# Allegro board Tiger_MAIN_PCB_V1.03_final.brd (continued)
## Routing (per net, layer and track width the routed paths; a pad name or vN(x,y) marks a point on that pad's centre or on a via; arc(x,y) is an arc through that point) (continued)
WIFI_PCIE_CLK_DP: length 146.9
  TOP w0.076: U1.C41 210.39,76.48 210.31,76.55 210.31,76.74 210.53,76.96 210.53,77.5 210.98,77.94 210.98,78.79 210.77,78.99 210.65,78.99 210.35,79.28 v2(210.35,79.37)
  TOP w0.109: v2(127.92,49.22) 127.73,49.03 127.73,36.09 127.07,35.43 127.07,30.21 127.43,29.86 127.43,26.24 126.18,25 125.29,25 125.15,24.86 CN26.47
  LAY6 w0.076: 189.88,79.4 195.09,79.4 195.83,80.15 201.63,80.15 202.57,81.09 202.57,81.37 202.84,81.64 204.11,81.64 206.24,79.51 207.45,79.51 207.98,78.98 209.96,78.98 v2(210.35,79.37)
  LAY6 w0.087: 189.88,79.4 181.76,79.4 180.68,80.48 176.34,80.48 174.97,79.11 172.69,79.11 171.94,79.87 168.04,79.87 167.59,80.32 164.72,80.32 164.05,79.64 160.51,79.64 158.5,77.64 150.89,77.64 149.24,75.99 144.86,75.99 144.08,75.21 134.96,75.21 134.65,75.52 129.16,75.52 128.96,75.72 128.96,76.09 v2(129.19,76.32)
  BOTTOM w0.109: v2(129.19,76.32) 128.96,76.1 128.96,75.44 127.73,74.2 127.73,49.41 v2(127.92,49.22)
WIFI_POWERON: length 113.7
  LAY3 w0.102: v2(63.45,63.17) 64.66,61.96 64.66,58.68 63.91,57.93 v2(63.91,35.78)
  LAY6 w0.102: v2(63.91,35.78) 64.31,36.18 78.61,36.18 79.01,35.77 80.7,35.77 81.73,36.8 84.4,36.8 91.01,43.42 93.67,43.42 97.68,47.43 107.03,47.43 109.12,45.33 112.37,45.33 114.69,43.02 118.26,43.02 118.88,42.4 127.4,42.4 134.85,34.95 v2(134.85,34.19)
  BOTTOM w0.102: v2(63.45,63.17) 63.16,63.46 U22.18 ; U19.3 135.39,34.19 R378.1 v2(134.85,34.19)
WIFI_RF_KILL_R*: length 3
  TOP w0.102: CN26.56 133.12,27.11 v2(133.3,26.92)
  BOTTOM w0.102: R3005.1 133.68,27.3 v2(133.3,26.92)
WIRELESS_ON: length 99.3
  LAY6 w0.102: v2(136.14,27.3) 136.14,27.31 136.62,27.8 136.62,33.89 127.39,43.12 119.44,43.12 119,43.56 115.02,43.56 112.67,45.91 109.95,45.91 107.82,48.04 97.06,48.04 93.71,44.69 86.96,44.69 86.05,45.6 66.63,45.6 61.63,50.61 v2(60.3,50.61)
  BOTTOM w0.102: U22.33 60.32,50.62 v2(60.3,50.61) ; R3005.2 v2(136.14,27.3)
WLAN_PCIE_WAKE*: length 104.5
  TOP w0.102: v2(190.56,59.53) 190.2,59.89 U1.AP7
  TOP w0.109: R95.2 172.96,59.18 v2(172.99,59.15) ; v2(120.8,55.47) 120.8,50.53 118.22,47.95 118.22,30.39 120.72,27.88 R3127.1
  LAY3 w0.076: 176.13,60.06 176.44,60.37 184.95,60.37 185.79,59.53 v2(190.56,59.53)
  LAY3 w0.087: 176.13,60.06 175.23,59.15 v2(172.99,59.15)
  LAY6 w0.087: v2(172.99,59.15) 172.24,58.4 166.72,58.4 165.91,57.59 164.71,57.59 163.9,58.4 160.01,58.4 159.28,57.67 ; 154.89,55.74 154.31,55.15 147.77,55.15 147.06,55.86 121.19,55.86 v2(120.8,55.47)
  LAY6 w0.102: 159.28,57.67 156.82,57.67 154.89,55.74
WLAN_PLT_RST: length 5.6
  TOP w0.102: v2(133.16,26.11) 133.11,26.11 133.11,26.11 CN26.52
  BOTTOM w0.102: U18.4 136.76,26.96 136.18,26.38 R155.1 133.44,26.38 v2(133.16,26.11)
WRST#: length 2.9
  TOP w0.102: v2(60.76,65.01) 60.76,64.69 61.04,64.41 R408.1 C481.2
  BOTTOM w0.102: U22.14 60.81,65.06 v2(60.76,65.01)
XCLK_BIASREF: length 9.4
  TOP w0.076: U1.E42 v2(210.68,74.32)
  TOP w0.102: v2(209.2,81.9) 209.82,81.9 R4.2
  LAY3 w0.102: v2(209.2,81.9) 209.85,81.25 209.85,75.15 v2(210.68,74.32)
XDP_BPM<2>: length 10.1
  TOP w0.076: TP22.1 218.61,83.82 218.61,79.65 217.71,78.75 217.71,77.2 U1.B54
XDP_BPM<3>: length 9.5
  TOP w0.076: TP23.1 219.22,83.43 219.22,79.54 218.17,78.49 218.17,76.42 U1.C56
XTAL1: length 9.2
  BOTTOM w0.102: U9.43 125.6,37.15 124.01,35.56 124.01,35.42 C372.1 124.28,35.08 123.86,34.65 123.86,30.89 X3.1
XTAL2: length 7.4
  BOTTOM w0.102: X3.3 123.61,32.52 123.61,34.62 C371.1 125.2,37.12 U9.44
XTAL24_IN: length 12.6
  TOP w0.102: U1.E37 208.23,75.49 208.23,75.62 208.25,75.64 208.25,76.01 208.23,76.03 208.23,76.27 208.25,76.29 208.25,76.6 207.92,76.93 207.92,77.88 207.6,78.19 207.6,78.45 207.38,78.67 207.38,81.77 R3.1 207.52,82.12 C1.1 207.52,83.2 207.1,83.61 207.1,84.75 X1.3
XTAL24_OUT: length 10.9
  TOP w0.102: X1.1 206.69,83.41 C2.1 206.69,82.03 R3.2 207.1,81.59 207.1,78.56 207.31,78.35 207.31,78.04 207.67,77.68 207.67,76.29 207.69,76.27 207.69,76.03 207.67,76.01 207.67,75.71 207.69,75.68 207.69,75.38 207.38,75.07 206.9,75.07 U1.E35
N26714753: length 9.3
  TOP w0.076: U1.BA15 195.07,55.33 195.33,55.08 195.33,53.98 191.37,50.02 191.37,49.35 190.95,48.93 R24.1 R9.2
N26714785: length 19.5
  TOP w0.076: U1.AN15 194.74,60.54 v2(195.13,60.15)
  TOP w0.102: R616.1 v2(181.33,52.26)
  LAY6 w0.076: v2(195.13,60.15) 194.63,59.65 193.97,59.65 193.66,59.34 193.66,57.54 191.15,55.02 185.79,55.02 185.26,54.49 184.51,54.49 182.22,52.2 181.7,52.2
  LAY6 w0.102: v2(181.33,52.26) 181.39,52.2 181.7,52.2
N26722992: length 14.5
  TOP w0.076: v2(177.24,70.03) 176.86,70.41 R56.1 ; v2(189.63,70.08) U1.N7
  LAY6 w0.076: v2(189.63,70.08) 189.18,70.54 188.09,70.54
  LAY6 w0.102: 188.09,70.54 184.32,70.54 183.86,71 178.21,71 v2(177.24,70.03)
N26723031: length 14.6
  TOP w0.076: R55.1 177.66,70.17 v2(177.8,70.03) ; U1.N8 v2(190.27,70.08)
  LAY6 w0.076: v2(190.27,70.08) 189.9,69.72 188.68,69.72 188.13,70.26
  LAY6 w0.102: 188.13,70.26 184.07,70.26 183.58,70.76 178.53,70.76 v2(177.8,70.03)
N26739346: length 12.2
  TOP w0.254: U1.G20 197.34,73.43 v2(196.96,73.05)
  LAY6 w0.254: v2(199.17,78.71) 198.75,78.29 198.75,75.75 199.26,75.24 199.26,74.43 198.01,73.19 197.1,73.19 v2(196.96,73.05)
  BOTTOM w0.305: v2(199.17,78.71) 199.19,78.74 199.19,80.42 198.66,80.96 R123.1
N26757648: length 3.8
  TOP w0.102: R711.2 176.21,51.1 R707.2 176.53,50.77 U42.7
N26757763: length 4.1
  TOP w0.102: U42.3 177.8,40.05 177.29,39.54 177.29,38.49 R709.2 R136.2
N26757791: length 3.2
  TOP w0.102: U42.2 176.53,38.96
  TOP w0.109: 176.53,38.96 R138.2
N26757807: length 2.9
  TOP w0.102: R139.2 179.06,48.25 U42.5
N26757835: length 7
  TOP w0.102: U42.6 177.8,46.75 177.98,46.57 178.3,46.57 178.47,46.73 178.47,50.48 R137.2
N29995527: length 9.8
  TOP w0.076: R75.2 182.9,52.44 184.43,53.97 186.78,53.97 187.33,54.52 187.33,55.05 187.5,55.22 187.5,55.56 187.7,55.76 187.97,55.76 188.11,55.9 188.11,56.46 188.87,57.23 U1.AW5
N30351746: length 7.6
  TOP w0.076: v2(220.42,82.71) 219.62,81.91 219.62,79.46 218.66,78.49 218.65,78.49 218.55,78.4 218.55,78.39 218.52,78.35 218.52,77.79 218.7,77.61 218.7,77.34 218.64,77.23 218.64,77.01 U1.B56
  BOTTOM w0.102: R39.2 220,82.71 v2(220.42,82.71)
N30351752: length 7.3
  TOP w0.076: v2(220.42,80.76) 220.03,80.36 220.03,79.36 219.51,78.85 219.51,77.83 219.36,77.68 219.36,77.32 219.39,77.22 219.39,77.03 219.36,76.94 219.36,76.69 219.37,76.64 219.41,76.49 219.49,76.21 219.49,76.09 219.57,75.83 U1.D59
  BOTTOM w0.102: R35.1 220.84,81.49 220.84,81.18 v2(220.42,80.76)
N30351756: length 8.5
  TOP w0.076: U1.A56 218.34,77.55 218.34,78.42 219.42,79.51 219.42,82.35 v2(220.42,83.36)
  BOTTOM w0.076: v2(220.42,83.36) 221.49,84.42 R31.1
N30351760: length 6.7
  TOP w0.076: U1.C59 219.6,76.46 219.52,76.71 219.52,76.89 219.58,77.08 219.58,77.23 219.52,77.34 219.52,77.61 219.69,77.78 219.69,78.73 220.41,79.45 220.41,80.09 v2(220.42,80.11)
  BOTTOM w0.102: R30.1 220.04,81.65 220.04,80.49 v2(220.42,80.11)
N30351779: length 6.4
  TOP w0.076: v2(222.23,80.76) 221.79,80.32 221.79,79.16 221.01,78.37 221.01,77.78 221.18,77.61 221.18,77.34 221.12,77.23 221.12,77.01 U1.B61
  BOTTOM w0.102: R40.2 222.7,81.58 222.7,81.23 v2(222.23,80.76)
N30351789: length 10.4
  TOP w0.076: R32.1 222.02,84.45 221.63,84.06 221.63,82.46 221.22,82.05 221.22,79.56 220.28,78.62 220.28,76.82 220.06,76.6 220.06,76.36 U1.D60
N30351793: length 6.5
  TOP w0.076: U1.A61 220.83,77.54 220.83,78.42 221.63,79.22 221.63,80.8 v2(222.23,81.41)
  BOTTOM w0.102: R33.1 222.6,82.34 222.6,81.77 v2(222.23,81.41)
N30351797: length 9
  TOP w0.076: R34.1 222.57,83.68 222.4,83.86 222.08,83.86 221.8,83.57 221.8,82.39 221.43,82.02 221.43,79.49 220.44,78.51 220.44,76.57 U1.C60
N30351801: length 20
  TOP w0.076: v2(222.23,82.06) 222.63,81.66 222.63,79.75 221.74,78.87 221.17,78.3 221.17,77.85 221.35,77.68 221.35,77.31 221.33,77.28 221.31,77.22 221.31,76.61 221.3,76.6 221.3,76.54 U1.C61 ; U1.B59 220.11,77.13 220.11,78.7 221.02,79.61 221.02,82.14 221.47,82.59 221.47,84.55 v2(222.23,85.31)
  LAY3 w0.102: v2(222.23,85.31) 221.86,84.93 221.86,82.43 v2(222.23,82.06)
N30362590: length 20.7
  TOP w0.102: v2(190.56,58.88) 190.2,59.24 U1.AR7
  TOP w0.109: v2(172.9,57.89) 172.97,57.96 R97.1
  LAY6 w0.076: 176.13,59.33 181.15,59.33 182.09,58.39 186.31,58.39 187.52,59.59 189.85,59.59 v2(190.56,58.88)
  LAY6 w0.087: v2(172.9,57.89) 174.3,57.89 175.74,59.33 176.13,59.33
N30362783: length 12.5
  TOP w0.076: U1.AD11 192.51,65.05 v2(192.81,64.75)
  BOTTOM w0.102: v2(192.81,64.75) 192.43,64.37 188.67,64.37 188.35,64.68 187.27,64.68 185.93,63.34 R98.2
N30362785: length 16.2
  TOP w0.076: U1.AD12 193.16,65.03 v2(193.44,64.75)
  BOTTOM w0.102: v2(193.44,64.75) 192.88,64.18 188.58,64.18 188.29,64.47 187.35,64.47 185.97,63.09 182.56,63.09 182.37,62.91 179.41,62.91 R99.2
N30362889: length 5
  TOP w0.076: U1.AN5 188.75,60.98 184.87,60.98 R101.1
N30418600: length 1.9
  TOP w0.076: U1.AK62 221.3,62.25 v2(220.16,63.38)
N30418602: length 1.2
  TOP w0.076: U1.AL61 220.73,62.12 220.21,62.64 v2(220.16,62.64)
N30475256: length 0.6
  TOP w0.076: U1.AM23 v2(200.62,60.8)
N30475258: length 1.8
  TOP w0.076: v2(199.7,60.8) U1.AM22
  BOTTOM w0.102: v2(199.7,60.8) 200.15,61.25 TP40.1
N30589381: length 2
  TOP w0.102: U6.1 169.42,54.3 R662.2 R663.1
N30589405: length 1.6
  TOP w0.203: C688.2 168.21,58.96 168.69,58.96 168.91,59.19 U67.6
N31076332: length 8.9
  TOP w0.076: U1.AW22 198.69,56.68 198.86,56.5 198.86,56.5 199.08,55.8 199.08,55.72 199.14,55.56 199.14,55.41 199.07,55.2 199.07,55.08 199.11,55 199.12,54.97 199.12,54.52 198.77,54.17 198.77,53.98 198.32,53.53 198.32,51.32 197.83,50.83 R623.2 R69.2
N31079742: length 4.7
  TOP w0.076: U1.BB5 188.93,54.7 188.61,54.7 188.06,54.16 187.58,54.16 186.67,53.25 TP43.1
N32032184: length 17.5
  TOP w0.076: U1.U6 v2(188.98,67.95)
  TOP w0.109: R111.2 174.2,67.79 v2(173.64,67.79)
  LAY3 w0.076: v2(188.98,67.95) 189.06,67.87 189.06,67.63 188.92,67.49 184.46,67.49 184.32,67.36 176.22,67.36
  LAY3 w0.102: v2(173.64,67.79) 174.07,67.36 176.22,67.36
N32032194: length 19.6
  TOP w0.076: U1.U7 v2(189.63,67.95)
  TOP w0.109: R110.2 174.01,66.79 v2(173.03,67.77)
  LAY3 w0.076: 176.13,67.07 184.27,67.07 184.51,67.31 189,67.31 v2(189.63,67.95)
  LAY3 w0.102: 176.13,67.07 173.72,67.07 v2(173.03,67.77)
N32032416: length 24
  TOP w0.076: v2(193.44,63.68) 193.16,63.97 U1.AF12
  TOP w0.109: v2(173.61,60.02) 173.07,60.56 R107.2
  LAY6 w0.076: 176.13,59.66 181.4,59.66 182.38,58.68 185.72,58.68 187.1,60.07 189.35,60.07 190.23,60.94 190.87,60.94 193.44,63.51 v2(193.44,63.68)
  LAY6 w0.102: 176.13,59.66 173.97,59.66 v2(173.61,60.02)
N32032433: length 23.2
  TOP w0.076: U1.AF11 192.51,63.98 v2(192.81,63.68)
  TOP w0.109: R106.2 173.63,60.74 v2(173.63,60.61)
  LAY6 w0.076: v2(192.81,63.68) 192.81,63.15 190.8,61.13 190.18,61.13 189.79,60.74 186.96,60.74 185.83,59.61 182.19,59.61 181.81,59.99 176.13,59.99
  LAY6 w0.102: v2(173.63,60.61) 174.25,59.99 176.13,59.99
N32034483: length 14.8
  TOP w0.076: U1.U8 v2(190.24,67.95)
  TOP w0.102: v2(178.44,68.33) 178.44,68.16 R108.2
  LAY6 w0.076: v2(178.44,68.33) 178.27,68.33 178.11,68.18 178.11,67.98 178.45,67.64 188.62,67.64 188.74,67.53 190.23,67.53 190.39,67.68 190.39,67.8 v2(190.24,67.95)
N32034499: length 15.3
  TOP w0.076: U1.U9 v2(190.89,67.95)
  TOP w0.102: v2(177.79,68.33) 177.59,68.53 177.59,68.63 R109.2
  LAY6 w0.076: v2(177.79,68.33) 177.79,68.04 178.37,67.46 188.57,67.46 188.68,67.35 190.29,67.35 v2(190.89,67.95)
N32256786: length 7.2
  TOP w0.102: U1.AW50 215.05,56.55 215.05,53.97 216.21,52.81 R3124.1
N32703185: length 10.8
  TOP w0.076: U1.B63 222.59,77.13 222.59,78.72 223.36,79.49 223.36,80.56 224.53,81.72 226.28,81.72 226.84,81.16 228.18,81.16 228.43,81.4 228.43,82.15 R122.2
N32759666: length 7.4
  TOP w0.076: v2(227.18,79.92) 226.7,79.92 226.32,80.31 224.55,80.31 224.08,79.84 224.08,79.2 223.3,78.41 223.3,77.8 223.28,77.79 223.28,77.68 223.39,77.57 U1.A65
  BOTTOM w0.102: TP21.1 227.23,79.97 v2(227.18,79.92)
N32938866: length 0.7
  TOP w0.102: U1.K32 v2(204.73,71.76)
N32938875: length 0.7
  TOP w0.102: U1.AK32 v2(204.73,62.87)
N32946040: length 6.2
  TOP w0.076: U1.BA5 189.13,55.3 189.32,55.1 189.32,54.67 189.17,54.51 188.69,54.51 188.14,53.97 187.67,53.97 185.81,52.11 185.81,51.9 R37.2
N33185602: length 1.8
  TOP w0.102: R827.2 171.01,80.62 R828.2 171.26,81.4 171.46,81.2 U56.3
N33386131: length 7
  TOP w0.076: TP45.1 181.96,70.36 181.96,69.85 182.3,69.5 185.14,69.5 185.69,68.95 186.86,68.95 U1.U2
N33386639: length 5.9
  TOP w0.076: TP44.1 181.98,69.34 183.93,69.34 184.49,68.78 R118.1
  TOP w0.102: R118.1 185.55,68.45 185.74,68.64 U1.U1
N33387416: length 4
  TOP w0.076: U1.N3 187.94,70.63 187.7,70.86 187.58,70.9 187.45,70.9 187.44,70.9 187.22,70.84 187.09,70.84 186.96,70.89 186.95,70.9 186.75,70.9 186.63,70.84 184.98,70.84 R117.1
N33387421: length 4.2
  TOP w0.076: U1.M4 188.21,71.02 187.74,71.02 187.59,71.08 187.44,71.08 187.22,71.01 187.11,71.01 186.99,71.06 186.97,71.08 186.76,71.08 186.57,71 184.67,71 R116.1
N34176799: length 11
  TOP w0.076: U1.C65 223.74,76.5 223.74,76.5 arc(223.81,76.58) 223.83,76.69 223.83,76.95 223.78,77.07 223.78,77.18 223.78,77.19 223.82,77.23 223.82,77.68 223.69,77.8 223.69,78.27 224.74,79.33 230.77,79.33 231.12,79.68 R36.2
N34374288: length 0.8
  BOTTOM w0.203: C7.1 R48.2
N34404832: length 0.8
  BOTTOM w0.203: C8.1 R49.2
N34544097: length 0.9
  TOP w0.109: C412.1 18.53,92.04 FIL7.1
N34544176: length 4.1
  TOP w0.109: D8.N 8.53,90.56 FIL5.3
  TOP w0.124: CN36.3 7.95,92.97 8.85,92.07 8.85,91.84 D8.N
N34544206: length 7.3
  TOP w0.109: FIL7.2 15.5,91.68 15.11,91.68 U14.2 14.72,92.07 13.94,92.07 13.31,91.44 12.28,91.44 12.04,91.69 12.04,91.99 12.95,92.91 CN36.9
N34544208: length 7.3
  TOP w0.109: CN36.8 10.95,92.92 11.82,92.06 11.82,91.6 12.19,91.22 13.52,91.22 13.84,90.9 14.69,90.9 U14.1 15.76,91.15 FIL7.3
N34544223: length 4.1
  TOP w0.109: D7.N 9.43,90.55 FIL5.2
  TOP w0.124: D7.N 9.11,91.84 9.11,92.11 9.95,92.96 CN36.2
N34544234: length 3.6
  TOP w0.109: U13.1 5.55,90.97 FIL6.3
  TOP w0.124: U13.1 4.95,92.14 CN36.5
N34544244: length 0.9
  TOP w0.109: C411.1 18.53,91.04 FIL7.4
N34544271: length 3.7
  TOP w0.109: FIL6.2 6.25,90.9 U13.2
  TOP w0.124: U13.2 6.95,92.25 CN36.6
N34559149: length 0.5
  BOTTOM w0.203: R429.2 127.82,82.38
N34559202: length 2.1
  BOTTOM w0.102: C490.2 129.23,81.57 R429.1 129.23,82.38 U25.4
N34566306: length 7.8
  BOTTOM w0.152: U22.2 60.93,69.86 60.75,70.03 60.75,70.56 61.8,71.61 61.8,72.56 R425.1 62.95,73.05 C484.1 63.5,73.18 63.73,72.95 X5.2
N34566379: length 8.3
  BOTTOM w0.152: X5.1 65.01,74 63.12,74 C482.1 63.02,74 R425.2 R424.2 61.5,73.99 61.5,71.69 60.68,70.87 60.45,70.87 60.32,71 U22.128
N34566418: length 3.4
  BOTTOM w0.102: U22.21 62.54,62.26 62.73,62.45 64.79,62.45 R416.1
N34566506: length 2
  BOTTOM w0.102: U22.90 45.13,67.86 R409.1
N34566519: length 4.4
  BOTTOM w0.102: U22.100 49.12,72.45 48.55,73.02 47.45,73.02 47.15,73.32 R421.1 R420.2
N34566620: length 3.6
  BOTTOM w0.102: R423.1 R422.2 50.45,73.26 50.63,73.08 51.07,73.08 51.52,72.63 U22.106
N34566783: length 1.4
  BOTTOM w0.102: U22.22 62.98,61.86 R401.1
N34566823: length 2.4
  TOP w0.102: U24.3 56.98,63.39 R428.1
N34566839: length 2.8
  TOP w0.102: U24.7 47.02,62.11 R427.1
N34566853: length 1.5
  BOTTOM w0.102: U22.12 63.27,65.86 C483.1
N34567017: length 1.4
  BOTTOM w0.102: R410.2 62.9,61.46 U22.23
N34567313: length 4.3
  BOTTOM w0.203: R398.1 65.53,66.34 62.72,66.34 62.64,66.26 U22.11
N34567537: length 9.2
  BOTTOM w0.102: U22.15 62.52,64.66 62.65,64.54 63.49,64.54 63.61,64.66 67.11,64.66 R403.2
N34567565: length 10.9
  BOTTOM w0.102: R457.1 69.81,60.31 R412.2 69.2,61.14 68.71,61.63 68.71,62.54 66.8,64.46 63.73,64.46 63.53,64.26 U22.16
N34567590: length 1.5
  BOTTOM w0.102: U22.82 45.76,64.66 45.57,64.85 R395.1
N34568048: length 2
  BOTTOM w0.102: U22.123 58.32,73.73 R413.1
N34568559: length 2.4
  BOTTOM w0.102: U22.107 51.92,72.7 51.22,73.4 R417.1
N34568586: length 226.6
  LAY3 w0.102: v2(63.21,89.86) 63.21,71.64 62.25,70.67 62.25,62.35 64.46,60.14 64.46,59.16 63.42,58.13 v2(63.42,57.52)
  LAY6 w0.102: v2(63.21,89.86) 64.06,89.01 88.51,89.01 90.85,86.67 104.29,86.67 105.56,87.94 119.15,87.94 121.43,90.23 127.49,90.23 129.99,87.73 133.83,87.73 135.27,86.28 142.16,86.28 150.47,94.59 170.08,94.59 171.65,93.02 179.97,93.02 181.16,91.83 190.56,91.83 191.31,92.58 200.56,92.58 201.38,91.77 201.38,91.41 205.87,86.91 207.29,86.91 207.94,86.27 215.78,86.27 218.03,84.03 218.03,80.12 219.36,78.79 223.18,78.79 225.3,80.91 226.6,80.91 228.55,82.86 232.06,82.86 v2(232.43,82.49)
  BOTTOM w0.102: R238.1 231.41,82.51 232.42,82.51 v2(232.43,82.49) ; U22.31 62.69,58.26 62.83,58.12 R466.1 v2(63.42,57.52)
N34568810: length 2.5
  BOTTOM w0.203: R236.1 44.99,57.03 45.25,57.29 45.25,57.69 45.82,58.26 U22.66
N34595104: length 16.9
  TOP w0.305: 116.43,34.02 116.47,34.02 116.73,33.75 ; 116.43,34.02 U11.4 ; 116.43,34.02 116.73,34.32 ; 116.73,37.07 116.65,36.99 116.29,36.99 ; 116.73,37.07 116.77,37.11 116.77,39.56 116.37,39.96 U11.10 ; 116.73,37.07 116.73,36.55 ; 116.29,36.99 115.97,36.99 115.97,36.99 U11.7 ; 116.29,36.99 116.73,36.55 ; 116.73,34.32 116.73,33.75 ; 116.73,34.32 116.73,36.55 ; 116.73,33.75 116.73,31.28 C398.2 U11.1
N34595477: length 31.1
  BOTTOM w0.097: CN10.7 88.05,24.24 90.17,24.24 91.23,23.19 95.88,23.19 98.09,25.39 98.09,36.79 102.61,41.31 103.37,41.31 FIL4.2
N34595569: length 30.6
  BOTTOM w0.097: CN10.5 88.06,20.76 95.56,20.76 98.93,24.13 98.93,35.49 102.06,38.63 103.42,38.63 FIL3.3
N34595612: length 1.3
  BOTTOM w0.102: R318.1 135.61,47.45 U10.2
N34595656: length 25.1
  TOP w0.097: CN10.6 89.28,20.81 92.79,20.81 97.22,25.24 97.22,33.77 99.17,35.72 99.93,35.72 100.03,35.82 100.03,35.95 100.12,36.05 FIL2.2
N34595663: length 24.3
  TOP w0.097: CN10.1 88.04,16.61 90.83,16.61 98.84,24.62 98.84,31.82 99.36,32.34 100.07,32.34 100.16,32.24 100.16,32.11 100.26,32.01 FIL1.3
N34595676: length 24.3
  TOP w0.097: FIL1.2 100.26,33.01 100.16,32.91 100.16,32.78 100.07,32.68 99.21,32.68 98.49,31.96 98.49,24.76 90.68,16.95 88.06,16.95 CN10.2
N34595746: length 25.1
  TOP w0.097: CN10.3 89.36,20.47 92.93,20.47 97.57,25.1 97.57,33.63 99.32,35.38 99.93,35.38 100.03,35.28 100.03,35.14 100.12,35.05 FIL2.3
N34595869: length 30.5
  BOTTOM w0.097: FIL3.2 103.42,38.28 102.2,38.28 99.27,35.35 99.27,23.98 95.7,20.42 88.04,20.42 CN10.4
N34595884: length 31.1
  BOTTOM w0.097: CN10.8 88.05,24.58 90.32,24.58 91.37,23.53 95.74,23.53 97.74,25.54 97.74,36.93 102.47,41.65 103.41,41.65 FIL4.3
N34596140: length 2.2
  BOTTOM w0.203: U8.4 113.71,45.38 C374.2 112.55,45.4 R306.1
N34600101: length 1.8
  BOTTOM w0.109: R362.1 18.98,18.36 U16.8
N34600137: length 4.2
  BOTTOM w0.203: FB13.2 19.84,23.1 C451.1 18.43,22.92 C452.2 17.43,22.76 U16.1
N34600193: length 2.1
  BOTTOM w0.102: C453.2 18.87,18.76 U16.7
N34600290: length 2.6
  BOTTOM w0.203: C445.2 12.93,14.65 13.25,14.97 13.75,14.97 14.33,15.55 U16.19
N34600339: length 1.2
  BOTTOM w0.203: C445.1 12.93,12.06 R3121.1
N34600341: length 1.1
  BOTTOM w0.203: R3120.1 11.71,11.8 C446.1
N34600347: length 3.2
  BOTTOM w0.203: U16.20 13.93,15.73 13.49,15.29 12.5,15.29 11.71,14.5 C446.2
N34600376: length 2.8
  BOTTOM w0.102: U16.13 16.73,15.8 17.5,15.03 R359.2 18.29,14.34 R358.2
N34600535: length 4.9
  BOTTOM w0.102: R370.2 20.66,27.82 R372.2 ; R372.2 20.23,27.82 19.76,27.35 U17.2 ; R372.2 21.42,27.82 21.65,28.06 Q19.3
N34600597: length 1.3
  BOTTOM w0.102: Q20.1 22.93,29.44 R373.1
N34600740: length 1.9
  BOTTOM w0.102: R357.1 16.71,14.6 15.93,15.38 U16.15
N34600742: length 3.8
  BOTTOM w0.203: U16.37 11.78,21.86 11.24,22.39 10.69,22.39 9.6,23.48 C443.1
N34600772: length 6.3
  BOTTOM w0.203: U16.34 7.25,20.36 6.28,21.33 C433.1
N34600774: length 7.2
  BOTTOM w0.203: U16.35 7.71,20.76 7.1,21.36 7.1,22.85 C443.2
N34600885: length 3.3
  BOTTOM w0.203: C436.1 10.22,15.6 10.48,15.86 10.48,17.01 11.03,17.56 U16.27
N34601042: length 2.5
  BOTTOM w0.203: U16.33 9.81,19.96 R349.2
N34601047: length 2.6
  BOTTOM w0.203: U16.32 10.29,19.56 9.41,18.68 R350.2
N34601410: length 8.9
  BOTTOM w0.102: Q20.3 22.77,33.2 23.45,32.52 23.45,29.65 23.7,29.4 R371.2 24.09,28.65 23.72,28.29 Q19.1
N34603029: length 2.1
  BOTTOM w0.102: U19.4 136.48,37.96 C470.2 136.46,38.75 R377.1
N34621634: length 1.3
  TOP w0.102: R611.2 Q49.3
N34621650: length 7.7
  TOP w0.102: R611.1 100.31,10.73 101.33,9.71 104.28,9.71 105.48,8.51 LED2.2
N34623411: length 2.6
  TOP w0.102: D18.N 160.39,15.82 161.29,16.72 Q47.1
N34623413: length 0.9
  TOP w0.203: C610.1 R609.1
N34852317: length 8
  TOP w0.076: R621.2 196.23,49.92 198.09,51.77 198.09,53.54 198.58,54.03 198.58,54.25 198.95,54.61 198.95,54.95 198.9,55.05 198.9,55.19 198.96,55.42 198.96,55.54 198.89,55.74 198.79,55.86 198.69,55.97 U1.AY22
N34852593: length 2
  TOP w0.102: R624.2 193.18,43.91 Q51.2 193.18,42.09 R626.2
N34852599: length 1.3
  TOP w0.102: R625.1 191.28,42.1 Q51.1
N34856886: length 5.6
  TOP w0.076: U1.B5 188.5,77.09 188.5,77.58 188.28,77.8
  TOP w0.102: R633.2 184.61,77.85 188.23,77.85 188.28,77.8
N34946454: length 4.1
  TOP w0.406: Q68.4 21.18,62.68 C802.2 21.18,63.46 R70.2 20.43,63.46 v2(19.73,64.17)
  BOTTOM w0.305: v2(19.73,64.17) 19.74,64.16 Q4.3
N35241025: length 2.1
  TOP w0.635: R765.2 158.93,55.03 159.5,55.61 Q55.8
N35241085: length 1.9
  TOP w0.635: R768.2 163,50.5 Q55.3
N35241097: length 2.1
  TOP w0.254: U41.2 165.06,44.05 165.58,43.53 R392.1
N35241124: length 1.5
  TOP w0.254: R762.1 160.26,45.38 U41.11
N35241153: length 2.8
  TOP w0.254: 165.68,45.38 U41.4
  TOP w0.508: R763.1 166.69,44.45 C761.2 166.68,45.38 165.68,45.38
N35249184: length 14
  TOP w0.635: R786.2 v1(18.92,84.77)
  BOTTOM w0.203: U71.15 16.76,73.06 17.23,73.53
  BOTTOM w0.635: v1(18.92,84.77) 18.9,84.76 18.9,75.2 17.23,73.53
N35249190: length 13
  TOP w0.635: R787.2 25.04,79.29 v1(24.54,79.79)
  BOTTOM w0.203: U71.16 17.36,72.31 17.37,72.31 17.83,72.77
  BOTTOM w0.635: v1(24.54,79.79) 23.5,79.79 20.93,77.22 20.93,75.75 17.95,72.77 17.83,72.77
N35249200: length 1.7
  BOTTOM w0.203: 18.03,72.07 17.7,71.74 U71.17
  BOTTOM w0.406: C767.1 18.55,72.07 18.03,72.07
N35249223: length 1.9
  BOTTOM w0.203: U71.9 14.2,71.74 13.94,72
  BOTTOM w0.406: C780.2 13.2,72 13.94,72
N35249239: length 2.1
  BOTTOM w0.203: D25.3 23,66.29 22.63,66.66 C779.2
N35249270: length 7.5
  BOTTOM w0.203: D24.2 26.57,69.09 C781.1 26.58,67.15 24.56,65.13 D25.1
N35249299: length 1.2
  BOTTOM w0.203: R780.1 18.07,70.07 17.6,70.54 U71.20
N35249362: length 1.4
  BOTTOM w0.102: R775.2 14.45,70.54 U71.6
N35249370: length 1.2
  BOTTOM w0.102: U71.7 14.33,70.94 13.84,70.44 R72.2
N35249515: length 10.5
  BOTTOM w0.203: U71.11 15.16,72.87 14.74,73.29
  BOTTOM w0.635: R781.1 14.87,80.71 15.65,79.93 15.65,78.42 13.99,76.75 13.99,74.05 14.74,73.29
N35249639: length 10
  TOP w0.635: v1(14.48,79.21) R783.1
  BOTTOM w0.203: 14.13,72.61 14.56,72.18 U71.10
  BOTTOM w0.635: 14.13,72.61 12.4,74.34 12.4,77.14 v1(14.48,79.21)
N35249877: length 5.4
  BOTTOM w0.203: 18.06,69.45 17.56,69.94 U71.1
  BOTTOM w0.305: 18.06,69.45 18.32,69.19 20.49,69.19 21.12,68.56 R778.2
N35250139: length 3.6
  BOTTOM w0.203: C770.2 24.76,68.31 24.49,68.31 D24.3
N35250147: length 2.7
  BOTTOM w0.203: 14.78,69.94 U71.5
  BOTTOM w0.305: R779.1 13.2,68.36 14.78,69.94
N35254494: length 4
  TOP w0.076: 196.59,44.11 196.59,45.44 Q59.1
  TOP w0.102: 196.59,44.11 R795.1
N35254509: length 1.4
  TOP w0.102: R796.2 195.63,41.53 Q59.3
N35256124: length 2.9
  BOTTOM w0.203: R773.2 157.17,46.84 R771.1 155.56,48.1 U70.6
N35256155: length 9.9
  LAY6 w0.305: v2(160.05,48.51) 157.08,48.51 155.01,46.44 v2(154.4,46.44)
  BOTTOM w0.203: R770.2 154.47,46.05
  BOTTOM w0.305: v2(160.05,48.51) 158.41,50.15 R772.1
N35256187: length 3.2
  BOTTOM w0.203: R825.1 155.58,45.21 155.58,46.63 155.21,47 R770.1 155.05,47.02 U70.7
N35256295: length 1.7
  BOTTOM w0.203: U70.5 156.03,50.75 156.63,50.15 R772.2
N35277788: length 1.9
  TOP w0.305: Q60.4 28.56,77.3 R807.1 C795.2
N35277870: length 2.3
  TOP w0.406: R810.1 C790.2 28.55,60.62 Q43.4
N35277915: length 1.2
  BOTTOM w0.305: R808.2 28.25,66.67 Q46.1
N35278836: length 5.5
  BOTTOM w0.102: R811.1 236.5,51.13 238.26,52.89 Q61.3
N35279533: length 1.6
  TOP w0.305: R817.1 38.16,74.99 Q63.3
N35279539: length 2
  TOP w0.305: Q64.3 37.06,63.17 R818.1
N35279545: length 1.3
  BOTTOM w0.406: Q52.3 231.66,44.1 R820.1
N35279549: length 1.4
  TOP w0.406: Q67.3 147.94,46.5 R819.1
N35279555: length 2.4
  TOP w0.305: Q66.3 182.44,87.1 182.81,86.74 R815.1
N35279596: length 1.3
  TOP w0.254: R816.1 157.89,69.72 Q53.3
N35557452: length 2
  BOTTOM w0.508: D31.P 88.43,79.12 88.01,79.54 R182.1
N35572372: length 5
  TOP w0.254: D26.N 158.38,43.26 R391.2 160.15,41.49 161.61,41.49 161.94,41.82 C344.2
N35765595: length 1.8
  BOTTOM w0.102: R102.1 44.76,63.46 U22.79
N35765799: length 2.1
  BOTTOM w0.102: U22.72 45.87,60.66 45.2,59.99 R104.2
N35765995: length 4.8
  TOP w0.102: U1.AB1 183.05,65.99 R112.1
N35766000: length 5.2
  TOP w0.102: U1.AB2 187.17,65.99 186.86,66.3 185.89,66.3 185.81,66.22 182.66,66.22 182.59,66.3 R105.1
N35767454: length 4
  TOP w0.076: U1.A7 190.05,78.08 189.3,78.83
  TOP w0.102: 189.3,78.83 188.25,79.88 R38.2
N35770734: length 8
  TOP w0.076: R134.2 182.85,67.99 186.07,67.99 186.41,68.33 188.29,68.33 188.48,68.14 U1.W4
N35770739: length 3.5
  TOP w0.102: U1.AB3 187.53,65.69 185.85,65.69 185.6,65.43 184.61,65.43 R77.2
N35788104: length 10.9
  TOP w0.076: v2(184.9,72.93) 184.9,73.45 184.63,73.72 R140.1 ; U1.L12 193.16,71.47 192.81,71.12 v2(192.81,71.02)
  LAY6 w0.102: v2(184.9,72.93) 185.28,72.55 188.35,72.55 189.15,71.75 192.2,71.75 192.81,71.14 v2(192.81,71.02)
N35805724: length 22.1
  TOP w0.102: v2(191.47,59.53) 191.38,59.53 U1.AP8
  LAY6 w0.076: 176.64,53.84 180.32,53.84 184.1,57.62 190.74,57.62 191.11,57.99 191.11,59.26 191.38,59.53 v2(191.47,59.53)
  LAY6 w0.102: 176.64,53.84 175.75,53.84 174.94,54.66 v2(174.02,54.66)
  BOTTOM w0.102: R142.2 174.01,54.66 v2(174.02,54.66)
N36034873:
  vias: v1(211.79,100.45) v1(212.59,100.45) v1(213.4,100.45)
N36034997: length 1.2
  BOTTOM w0.508: C740.2 163.05,89.87 R258.2
N36035123: length 1.6
  TOP w0.635: Q73.8 159.88,90.74 159.88,92.37 R183.1
N36035170: length 3
  BOTTOM w0.203: U103.2 235.34,87.44 233.41,87.44 C308.2 R669.1
N36035178: length 4.7
  TOP w0.305: R667.2 C717.1 C324.2 R208.2 234.79,83.25 233.95,84.1 R591.1
N36035212:
  vias: v1(172.59,98.68) v1(173.35,98.68) v1(174.11,98.68) v1(174.88,98.68)
N36035226: length 5.2
  BOTTOM w0.203: R220.2 C722.1 238.17,95.85 U103.16
N36035247: length 0.9
  BOTTOM w0.203: C303.1 242.35,95.13 R216.1
N36035348: length 4.1
  BOTTOM w0.305: R222.1 238.41,99.89 C305.2 239.45,100.92 ; R683.1 239.42,101.93 R681.1 239.42,100.95 239.45,100.92 ; 239.45,100.92 C719.2
N36035428: length 3.2
  BOTTOM w0.203: U103.14 237.37,93.18 R680.2 C316.1
N36035485: length 1.5
  TOP w0.635: v1(182.26,101.93) Q69.4
  BOTTOM w0.635: R689.2 182.26,101.19 v1(182.26,101.93)
N36035580: length 5.2
  BOTTOM w0.203: R217.2 243.41,94.17 R216.2 241.37,93.2 240.73,93.2 239.77,92.24 U103.20
N36035694: length 5.2
  BOTTOM w0.203: R678.2 236.36,95.59 236.78,95.18 237.16,95.18 237.77,94.56 U103.15
N36035696: length 1.1
  BOTTOM w0.203: R229.2 236.36,96.83 R678.1
N36035835: length 0.8
  BOTTOM w0.203: R213.1 244.29,101.36 244.29,101.35
N36035841: length 2.3
  BOTTOM w0.203: R671.1 233.56,87.85 235.36,87.85 U103.3
N36035843: length 1.1
  BOTTOM w0.305: R671.2 231.28,88.12 R219.1
N36035870: length 4.2
  BOTTOM w0.203: U103.32 239.37,85.99 241.19,84.17 241.68,84.17 R234.2
N36036104: length 1.2
  BOTTOM w0.635: R239.1 181.63,95.97 181.63,97.17 C721.1
N36036129: length 2.8
  BOTTOM w0.203: R235.2 241.26,85.22 240.76,85.22 239.77,86.21 U103.31
N36036375: length 0.8
  BOTTOM w0.305: C314.1 R226.1
N36036466: length 0.8
  BOTTOM w0.305: C719.1 R227.1
N36036545: length 0.9
  BOTTOM w0.203: C309.1 R220.1
N36036623: length 8.7
  TOP w0.305: v2(235.72,85.03) 235.93,84.82 R210.1
  TOP w0.406: R209.1 237.01,83.25 R208.1 R210.1
  LAY3 w0.305: v2(235.72,85.03) 235.53,85.03 234.31,86.25 234.31,88.54 v2(234.25,88.6)
  BOTTOM w0.203: v2(234.25,88.6) 234.37,88.72 U103.5
N36036629: length 0.9
  TOP w0.406: C302.2 234.94,84.11 R210.2
N36036665: length 1
  BOTTOM w0.203: C299.2 243.29,99.35 R244.2
N36036687: length 11.7
  TOP w0.406: v2(238.14,85.17) 238.24,85.08 C306.2 238.47,83.46 R590.2 238.47,81.58 R668.2
  LAY3 w0.305: v2(238.14,85.17) 237.69,85.17 234.96,87.91 234.96,88.58 234.31,89.22 v2(233.88,89.22)
  BOTTOM w0.203: v2(233.88,89.22) 234.42,89.22 234.52,89.12 U103.6
N36036762: length 2.9
  BOTTOM w0.406: C294.2 232.51,95.82 230.56,95.82 230.25,96.12 R168.2
N36036804: length 0.9
  BOTTOM w0.305: R206.2 R205.1
N36036974: length 4
  BOTTOM w0.203: R211.1 232.88,90.13 C300.2 233.1,89.12 234.07,88.16 234.5,88.16 234.66,88.32 U103.4
N36037016: length 1.1
  BOTTOM w0.305: R211.2 C301.2
N36037139: length 1.3
  TOP w0.406: R209.2 236.94,81.68 C717.2
N36037141: length 3
  BOTTOM w0.203: R674.2 245.46,97.51 R672.1 246.29,96.44 C318.1 R230.1
N36037149: length 6.5
  BOTTOM w0.203: R231.1 246.45,89.66 246.45,94.67 246.29,94.83 C318.2
N36037438: length 1.1
  BOTTOM w0.203: C313.1 243.47,92.34 R224.1
N36037621: length 5.6
  BOTTOM w0.203: 234.28,90.48 234.85,89.92 U103.8
  BOTTOM w0.305: C295.2 232,92.75 R212.1 232.67,92.44 232.92,92.18 233.62,92.18 234.28,91.52 234.28,90.48
N36037625: length 0.9
  BOTTOM w0.305: R207.1 232,93.7 C295.1
N36037871: length 1.1
  BOTTOM w0.635: C738.2 213.27,96.83 R249.2
N36037926: length 1.9
  BOTTOM w0.203: C806.1 244.02,82.95 244.02,82.34 243.73,82.05 R228.2
N36059207: length 2.2
  BOTTOM w0.305: R794.1 152.53,17.9 Q56.3
N36084711: length 0.9
  BOTTOM w0.203: C700.2 159.74,60.98 U59.6
N36086308: length 1.2
  TOP w0.254: U56.6 C808.2
N36091446: length 3.2
  TOP w0.305: U35.2 R534.1 R536.2
N36093005: length 1.4
  TOP w0.406: U35.8 142.3,55.73 R535.1
N36133789: length 3.4
  TOP w0.203: Q74.3 46.72,69.15 46.36,69.51 R829.2 Q1.1
N36535071: length 8.8
  TOP w0.076: U1.AM5 v2(189.53,61.54)
  TOP w0.102: v2(182.64,59.98) 182.36,60.26 R255.2
  LAY6 w0.076: v2(182.64,59.98) 183.08,60.41 186.17,60.41 186.71,60.94 188.49,60.94 189.08,61.54 v2(189.53,61.54)
N36535773: length 0.9
  TOP w0.102: R264.1 R255.1
N36703241: length 3.3
  TOP w0.203: CN1.166 196.11,15.18 v2(196.12,15.18)
  BOTTOM w0.254: R435.1 R386.1 196.12,15.18 v2(196.12,15.18)
N36703730: length 2.6
  TOP w0.102: v2(206.22,15.5) 206.11,15.4 CN1.134
  BOTTOM w0.076: R385.2 206.22,14.87 v2(206.22,15.5)
N36791597: length 8.6
  TOP w0.102: R512.1 C274.2 228.85,50.85 226.17,53.53 225.11,53.53 224.43,54.21 224.43,55.16 U1.BA67
N36791664: length 0.8
  TOP w0.102: C274.1 R513.2
N36887704: length 5.6
  TOP w0.109: R521.2 242.97,69.87 241.82,68.72 Q26.3 242.77,67.01 Q26.1
N36887763: length 2.4
  TOP w0.109: R522.1 C669.2 243.81,72.5 U5.3
N36887773: length 1.7
  TOP w0.109: R522.2 Q26.2
N36887775: length 2.4
  TOP w0.109: U5.2 243.16,72.58 C669.1 R521.1
N36901448: length 4.3
  BOTTOM w0.102: U22.104 50.72,72.46 50.4,72.78 49.41,72.78 48.81,73.37 R458.1 R462.1
N36968587: length 3.9
  TOP w0.635: Q71.4 216.55,100.38 v1(216.58,100.42)
  BOTTOM w0.635: R254.2 216.06,97.93 216.58,98.45 v1(216.58,100.42)
N36968684: length 1.6
  TOP w0.635: Q72.4 v1(222.09,93.63)
  BOTTOM w0.635: v1(222.09,93.63) R256.2
N36971587: length 3
  BOTTOM w0.305: U21.2 184.81,28.21 R469.2 185.08,28.47 R464.1
N36971629: length 2.6
  BOTTOM w0.203: R470.1 176.15,30.35 R270.1 176.23,29.48 U21.8
N36971657: length 1.8
  BOTTOM w0.305: U21.7 177.2,28.21 176.78,28.62 R271.2
N36979254: length 3.9
  TOP w0.102: v2(214.89,19.95) 215.36,20.42 CN1.97
  BOTTOM w0.102: R471.1 215.34,21.15 215.34,20.39 v2(214.89,19.95)
N36979257: length 3.1
  TOP w0.102: CN1.95 215.86,20.34 v2(216.03,20.17)
  BOTTOM w0.102: R472.1 215.91,21.27 215.91,20.29 v2(216.03,20.17)
N37048296: length 4.9
  BOTTOM w0.102: U22.4 65.09,69.06 65.58,69.55 65.58,69.77 R487.1
N37063122: length 1.7
  BOTTOM w0.203: U29.25 234.99,35.37 v2(234.99,35.37)
  BOTTOM w0.406: v2(234.99,35.37) C697.1
  vias: v1(238.69,33.75) v1(238.7,32.98) v1(239.45,33.75) v1(239.46,32.98) v1(240.23,34.55) v1(240.21,33.75) v1(240.23,32.98) v2(238.28,35.93) v2(238.33,37.83) v2(238.64,36.28) v2(238.84,37.83)
N37063333: length 1.6
  BOTTOM w0.203: R543.1 241.53,37.77 U29.10
N37063789: length 4.7
  BOTTOM w0.102: U29.8 239.35,39.41 239.86,39.91 240.76,39.91 R544.1 242.74,41.08 R545.1
N37064197: length 3.5
  BOTTOM w0.203: C697.2 233.39,36.01 235.02,36.01 235.18,36.17 U29.27
N37066595: length 5.1
  BOTTOM w0.203: 235.48,39.56 236.21,38.82 U29.1
  BOTTOM w0.305: 235.48,39.56 235.48,40.56 233.93,42.1 C703.2
N37068393: length 5.7
  BOTTOM w0.203: U29.3 237.35,39.25 236.74,39.87
  BOTTOM w0.305: 236.74,39.87 235.94,40.67 C704.1 235.94,43.15 R547.1 235.94,43.94 R546.1
N37069902: length 3.2
  BOTTOM w0.102: U29.6 238.55,39.95 239.11,40.51 R548.1 239.88,41.07 R552.2
N37069925: length 3.6
  BOTTOM w0.102: R551.2 237.54,43.72 236.77,44.49 Q21.3
N37070732: length 3.7
  BOTTOM w0.203: U29.7 238.95,39.72
  BOTTOM w0.305: R553.2 240.88,40.84 240.4,40.37 239.6,40.37 238.95,39.72
N37076872: length 2.1
  BOTTOM w0.102: R419.1 45.02,57.88 45.8,58.66 U22.67
N37309832: length 5.3
  TOP w0.109: FIL10.2 D19.N 64.8,20.07 64.91,20.18 64.91,20.35 65.02,20.46 67.31,20.46 CN23.2
N37309834: length 5.4
  TOP w0.109: FIL10.3 D20.N 64.8,21.07 64.91,20.96 64.91,20.79 65.02,20.68 67.15,20.68 CN23.3
N37310702: length 5.2
  TOP w0.109: FIL9.4 48.91,20.02 D21.N 49.22,20.03 49.33,20.14 49.33,20.31 49.44,20.42 51.64,20.42 52.4,19.66 CN22.2
N37310717: length 5.4
  TOP w0.109: CN22.3 52.4,21.34 51.7,20.64 49.44,20.64 49.33,20.75 49.33,20.92 49.22,21.03 D22.N 48.91,21.02 FIL9.1
N37310916: length 4
  TOP w0.109: R2981.2 35.99,91.18 35.99,91.44 D2513.N 36.85,92.3 CN24.2
N37310918: length 4
  TOP w0.109: CN24.5 31.85,92.25 32.46,91.64 U2523.1 32.58,91.19 32.58,90.73 FIL16.3
N37310933: length 1
  TOP w0.124: C2762.1 42.65,89.32 FIL14.4
N37310942: length 4
  TOP w0.109: FIL16.2 33.16,90.71 U2523.2 33.16,91.66 33.85,92.35 CN24.6
N37310944: length 6.2
  TOP w0.109: R2979.2 40.06,90.32 39.57,89.83 39.31,89.83 39.13,90.01 U2524.2 38.87,90.18 38.72,90.34 38.72,90.82 39.85,91.95 CN24.9
N37310966: length 1
  TOP w0.124: C2763.1 42.3,90.32 41.69,90.32 FIL14.1
N37310979: length 4
  TOP w0.109: CN24.3 34.85,92.32 D2512.N 35.73,91.44 35.73,91.18 R2980.2
N37311057: length 6.2
  TOP w0.109: R2978.2 39.78,89.48 U2524.1 39.13,89.61 38.5,90.24 38.5,90.95 37.85,91.6 CN24.8
N37376325: length 14.1
  TOP w0.305: J3.4 34.64,28.35 34.36,28.07 31.23,28.07 30,29.29 30,30.57 C418.1 27.76,31 26.22,29.46 R366.1
N37376350: length 4
  BOTTOM w0.305: J2.4 36.54,18.94 36.83,19.23 C414.1 R347.1
N37376400: length 4.1
  BOTTOM w0.305: J2.3 28.54,18.76 29.12,19.33 R348.1 C413.1
N37376460: length 5.3
  TOP w0.305: R365.1 25.41,25.8 C419.1 27.48,25.8 28.54,26.86 J3.3
N37412625: length 3.2
  TOP w0.203: R2985.2 R2997.2 139.34,89.3 v2(138.55,88.51)
  BOTTOM w0.203: U2526.45 v2(138.55,88.51)
N37412638: length 1.8
  BOTTOM w0.102: U2526.20 140.95,79.06 R2984.1
N37413349: length 1.7
  TOP w0.203: R2988.1 131.27,78.39 U2527.7
N37416123: length 3
  TOP w0.102: v2(133.3,27.62) 133.3,27.61 CN26.58
  BOTTOM w0.102: v2(133.3,27.62) 133.84,28.15 R3000.1
N37416136: length 3.1
  TOP w0.102: CN26.60 133,28.11 v2(133.24,28.35)
  BOTTOM w0.102: R3001.1 133.84,28.95 v2(133.24,28.35)
N37416331: length 2
  TOP w0.102: CN26.50 v2(130.53,25.61)
  BOTTOM w0.102: R3004.1 130.71,25.43 v2(130.53,25.61)
N37456108: length 1.3
  TOP w0.305: R3098.1 122.69,79 R3102.2
N37456113: length 1.4
  TOP w0.305: R3099.1 R636.2
N37456118: length 1.4
  TOP w0.305: R3100.1 R756.2
N37456123: length 1.4
  TOP w0.305: R3101.1 R755.1
N37456573: length 3.2
  TOP w0.203: Q76.3 134.44,86.53 Q48.1 133.07,85.37 R3108.2
N37456813: length 31.4
  TOP w0.305: R3091.1 v2(123.12,83.13)
  LAY3 w0.305: v2(123.12,83.13) 122.67,83.57 104.02,83.57 v2(103.23,82.79)
  BOTTOM w0.305: v2(103.23,82.79) 102.75,83.27 101.82,83.27 R3117.2 R3116.2 R3115.2 R3114.2 103.31,89.18 Q95.2
N37456912: length 27.9
  TOP w0.305: v2(128.48,83.32) 128.64,83.32 128.92,83.6 R606.2
  LAY3 w0.508: v2(104.13,82.25) 127.41,82.25 v2(128.48,83.32)
  BOTTOM w0.508: v2(104.13,82.25) 104.13,83.78 Q95.1
N37457475: length 5.4
  BOTTOM w0.406: R3118.1 88.53,90.57 90.19,92.22 91.71,92.22 92.12,91.81 J5.5
N37457477: length 4.6
  BOTTOM w0.406: J5.6 90.14,91.06 89.02,89.94 87.83,89.94 87.36,90.4 R3097.1
N37458124: length 3.6
  TOP w1.016: CN3.P7 99.48,57.23 v1(99.31,57.39)
  BOTTOM w0.762: R748.2 99.65,57.39 v1(99.31,57.39)
N37458279: length 4.6
  TOP w0.109: CN3.S5 102.94,73.74 103.05,73.63 103.05,73.32 103.16,73.21 103.5,73.21 104.52,72.19 104.87,72.19 C2840.2
N37458285: length 4.4
  TOP w0.109: CN3.S2 102.94,77.55 103.05,77.44 103.05,77.13 103.16,77.02 103.91,77.02 104.29,77.4 104.29,77.71 104.01,78 C2842.2
N37458287: length 4.8
  TOP w0.109: C2843.2 104.8,78 104.51,77.71 104.51,77.31 104,76.8 103.16,76.8 103.05,76.69 103.05,76.38 102.94,76.28 CN3.S3
N37458304: length 4.6
  TOP w0.109: C2841.2 104.89,71.97 104.43,71.97 103.41,72.99 103.16,72.99 103.05,72.88 103.05,72.57 102.94,72.47 CN3.S6
N37481490: length 2.3
  BOTTOM w0.102: U22.109 52.72,72.38 52.01,73.09 R3122.2
N37491665: length 1.3
  TOP w0.305: R452.2 131.26,83.45 U27.4
N37619180: length 9.2
  TOP w0.102: U1.AT52 216.06,58.24 216.06,57.64 215.7,57.28 215.7,54.75 217,53.45 R3125.1
N37654536: length 3.6
  TOP w0.102: R3126.2 R3127.2 122.88,26.86 CN26.55
N37689085: length 15.5
  TOP w0.102: R175.2 76.05,54.24 74.62,52.8 74.62,47.38 78.08,43.92 CN5.38
N37689147: length 4
  TOP w0.102: R199.2 R174.1 R240.1 88.88,36.17 CN5.69
N37689278: length 2.4
  TOP w0.109: R187.2 88.71,39.76 88.43,39.76 88.17,40.03 87.81,40.03 87.67,40.17 CN5.53
N37689280: length 2.4
  TOP w0.109: R194.2 88.71,39.54 88.71,39.54 88.34,39.54 88.08,39.81 87.84,39.81 87.69,39.67 CN5.55
N37689443: length 4
  TOP w0.109: R198.2 89.75,43.04 89.37,42.67 CN5.43
N37689445: length 4
  TOP w0.109: CN5.41 87.7,43.17 87.98,42.88 89.28,42.88 89.53,43.13 89.53,43.37 88.96,43.94 R197.2
N37689471: length 2.4
  TOP w0.109: C338.1 88.76,41.14 88.31,41.14 88.17,41.28 87.96,41.28 87.85,41.17 CN5.49
N37689473: length 2.4
  TOP w0.109: CN5.47 87.79,41.67 87.95,41.5 88.26,41.5 88.4,41.36 88.72,41.36 C333.1
N37689619: length 17.6
  TOP w0.102: R200.2 78.54,55.46 80.94,53.06 80.94,41.42 80.43,40.92 CN5.50
N37690406: length 134.3
  TOP w0.076: U1.A23 199.96,77.72 200.63,78.38 200.63,78.53 200.44,78.72 v2(200.38,78.72)
  TOP w0.109: C326.1 90.33,50.35 91.25,50.35 v2(91.44,50.15)
  LAY3 w0.076: v2(200.38,78.72) 200.19,78.72 200.08,78.82 200.08,78.99 200.21,79.12 200.7,79.12 200.79,79.2 200.79,79.41 200.65,79.55 198.91,79.55 196.75,81.71 191.37,81.71 190.44,80.78 189.92,80.78 189.91,80.77 189.9,80.77
  LAY3 w0.087: 189.9,80.77 188.79,80.77 187.14,79.12 177.27,79.12 176.05,77.9 176.05,75.23 173.98,73.17 165.33,73.17 164.36,74.13 153.1,74.13 147.87,68.9 142.75,68.9 141.1,67.25 134.43,67.25 130.97,63.78 113.61,63.78 113.19,63.36 98.33,63.36 92.25,57.28 92.25,50.78 91.95,50.49 91.77,50.49 v2(91.44,50.15)
N37690408: length 134.3
  TOP w0.076: v2(200.95,78.72) 200.79,78.56 200.79,78.31 200.23,77.75 200.23,77.07 U1.B23
  TOP w0.109: C322.1 90.32,50.56 91.25,50.56 v2(91.44,50.76)
  LAY3 w0.076: 189.9,80.95 189.91,80.95 189.92,80.95 190.37,80.95 191.3,81.87 196.82,81.87 198.98,79.71 200.72,79.71 200.95,79.48 v2(200.95,78.72)
  LAY3 w0.087: 189.9,80.95 188.72,80.95 187.07,79.3 177.19,79.3 175.86,77.97 175.86,75.31 173.91,73.35 165.4,73.35 164.44,74.32 153.03,74.32 147.79,69.08 142.68,69.08 141.03,67.43 134.36,67.43 130.89,63.97 113.53,63.97 113.11,63.55 98.25,63.55 92.06,57.36 92.06,50.86 91.87,50.67 91.53,50.67 v2(91.44,50.76)
N37690460: length 4.7
  TOP w0.076: U1.D23 199.68,75.78 199.68,76.3 199.54,76.6 199.54,77.86 199.76,78.08 199.76,78.71 199.45,79.01 C327.1
N37690481: length 4.7
  TOP w0.076: U1.C23 199.85,76.27 199.85,76.33 199.71,76.64 199.71,77.79 199.92,78.01 199.92,78.78 199.62,79.08 199.62,79.25 199.71,79.34 200.29,79.34 200.39,79.43 200.39,79.67 C330.1
N37690514: length 4.8
  TOP w0.076: U1.D24 200.53,76.02 200.83,76.32 200.83,76.67 200.69,76.81 200.69,77.56 201.96,78.83 201.96,79.43 C331.1
N37690535: length 4.8
  TOP w0.076: C332.1 201.79,79.45 201.79,78.9 200.53,77.63 200.53,76.95 200.22,76.64 200.22,76.31 200.31,76.22 200.45,76.22 200.53,76.3 U1.C24
N37690970: length 19.6
  TOP w0.102: R3128.2 74.8,53.33 74.39,52.92 74.39,42.99 77.46,39.92 CN5.54
N37767624: length 9.1
  BOTTOM w1.016: R303.1 118.53,13.85 CN9.D
N37788612: length 2.7
  TOP w0.635: Q70.4 188.54,95.22 v1(188.52,95.2)
  BOTTOM w0.635: R690.2 188.52,94.97 v1(188.52,95.2)
N37895377: length 1.3
  BOTTOM w0.203: R225.2 245.68,80.6 R221.2
N360368650: length 7.8
  BOTTOM w0.203: C718.1 247.08,89.3 246.22,88.43 R185.1
N374569031: length 0.8
  TOP w0.203: R3093.2 129.71,87.19 C2834.2
N3524071713: length 2.5
  TOP w0.254: U41.14 162.53,43.14 161.6,42.21 R391.1

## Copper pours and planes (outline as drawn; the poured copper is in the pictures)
+V1.5S on TOP (solid shape): 151.03,51.37 151.03,49.75 150.81,49.53 145.9,49.53 145.78,49.65 145.78,51.43 145.92,51.57 150.83,51.57
+V1.8U_2.5U_MEM on TOP (solid shape): 173.53,23.07 173.53,20.86 173.31,20.65 172.45,20.65 171.89,21.2 171.89,23 172.19,23.3 173.3,23.3
+V1.8U_2.5U_MEM on BOTTOM (solid shape): 189.91,26.74 189.91,22.07 188.91,21.07 181.55,21.07 180.53,22.1 173.2,22.1 172.88,21.78 171.84,21.78 171.7,21.92 171.7,23.12 171.81,23.24 181.1,23.24 182.02,22.32 187.82,22.32 188.33,22.83 188.33,24.64 187.97,25.01 182.25,25.01 181.95,25.31 181.95,27.24 181.97,27.27 189.38,27.27
+V1P00A on TOP (solid shape): 172.26,82.39 172.26,81.66 172.17,81.58 171.64,81.58 171.36,81.86 170.87,81.86 170.79,81.94 170.79,82.48 170.88,82.57 172.09,82.57
+V1P00A on TOP (solid shape): outline of 193 points within 159.86,61.32 185.94,82.92
+V1P00A on BOTTOM (solid shape): 195.92,75.51 195.92,75.26 195.89,75.24 195.72,74.99 195.83,74.71 195.86,74.64 195.83,74.56 195.72,74.28 195.89,74.03 195.92,74.02 195.92,73.21 195.99,73.14 195.99,72.67 196.27,72.39 196.27,71.94 196.51,71.7 196.51,71.44 196.47,71.4 196.11,71.4 196.09,71.41 196.08,71.42 195.85,71.65 195.85,72.19 195.64,72.4 195.64,72.82 195.54,72.82 195.46,72.86 195.44,72.95 195.41,73.22 195.18,73.37 195.14,73.38 195.14,75.29 194.66,75.76 194.65,75.79 194.65,75.82 194.58,76.22 194.18,76.29 194.15,76.29 194.12,76.3 193.66,76.76 193.64,76.87 193.74,76.93 194.5,76.93
+V1P00A on BOTTOM (solid shape): 196.57,76.43 196.57,76.23 196.47,75.85 196.78,75.61 196.8,75.61 196.85,75.56 196.85,75.33 196.82,75.28 196.61,75.02 196.7,74.7 196.73,74.64 196.6,74.32 196.7,74.07 196.73,74.03 196.73,73.93 196.72,73.92 196.63,73.7 196.72,73.48 196.73,73.47 196.73,73.34 196.7,73.3 196.61,72.98 196.82,72.72 196.85,72.68 196.85,72.17 197.14,71.88 197.14,71.48 197.06,71.41 196.83,71.41 196.71,71.53 196.71,71.79 196.48,72.02 196.48,72.47 196.2,72.75 196.2,73.19 196.12,73.26 196.12,74 196.16,74.01 196.37,74.25 196.27,74.56 196.23,74.64 196.27,74.71 196.37,75.02 196.16,75.26 196.12,75.27 196.12,75.6 194.25,77.47 194.25,77.61 194.45,77.81 195.18,77.81
+V1P00A on BOTTOM (solid shape): outline of 309 points within 195.67,69.6 198.65,78.59
+V1P00A on BOTTOM (solid shape): outline of 856 points within 174.01,64.14 197.8,66.86
+V1P00A on BOTTOM (solid shape): outline of 1296 points within 174.16,58.42 200.65,68.54
+V1P00A on BOTTOM (solid shape): outline of 3457 points within 164.47,64.71 199.13,76.55
+V1P00A on LAY3 (solid shape): outline of 208 points within 196.76,63.28 200.18,68.6
+V1P00A on LAY4 (solid shape): outline of 1534 points within 164.7,64.91 197.46,72.38
+V1P00A on LAY4 (solid shape): outline of 2479 points within 169.77,69.48 198.49,81.52
+V1P00A on LAY4 (solid shape): outline of 2667 points within 179.29,56.51 199.27,68.95
+V1P00S_VCCSTG on TOP (solid shape): 170.5,59.95 170.6,59.93 170.71,59.95 170.72,59.95 171.14,59.95 171.52,59.57 171.52,58.15 171.89,57.78 171.89,56.42 171.61,56.14 169.79,56.14 169.52,56.41 169.52,57.87 169.24,58.15 169.24,59.77 169.42,59.95 170.49,59.95
+V1P00S_VCCSTG on BOTTOM (solid shape): outline of 140 points within 200.81,59.07 205.64,63.71
+V1P00S_VCCSTG on LAY4 (solid shape): outline of 3614 points within 168.69,50.3 211.21,61.84
+V1P8A on TOP (solid shape): 152.18,57.82 152.18,56.19 151.72,55.74 149.57,55.74 149.43,55.88 149.43,58.19 149.65,58.4 151.59,58.4
+V1P8A on BOTTOM (solid shape): 170.99,67.64 170.99,67.19 170.82,67.01 170.82,66.21 170.67,66.06 169.61,66.06 169.46,66.21 169.46,67.47 169.7,67.71 170.93,67.71
+V1P8A on BOTTOM (solid shape): 155.34,62.2 155.34,61.1 155.8,60.63 157.22,60.63 157.35,60.5 157.35,55.11 156.88,54.63 152.34,54.63 150.87,56.1 150.87,58.83 154.56,62.53 155.01,62.53
+V1P8S on BOTTOM (solid shape): 161.9,60.44 161.9,59.11 161.76,58.97 159.42,58.97 158.65,59.74 158.65,60.54 158.75,60.64 161.69,60.64
+V3.3_LAN on BOTTOM (solid shape): 119.99,48.12 119.99,46.01 119.91,45.92 118.47,45.92 118.23,46.16 118.23,46.53 117.95,46.81 117.18,46.81 116.99,47 115.61,47 115.47,47.14 115.47,48.12 115.6,48.24 119.87,48.24
+V3.3_WIFI on TOP (solid shape): 134.99,32.32 134.99,29.43 135.41,29.02 135.41,24.34 134.54,23.47 134.54,9.14 133.29,7.9 129.99,7.9 129.84,8.05 129.84,9.06 130.04,9.27 130.04,11.34 130.4,11.69 130.4,12.99 130.07,13.32 130.07,13.95 130.4,14.28 132.54,14.28 132.57,14.26 132.57,13.97 132.54,13.94 130.99,13.94 130.97,13.91 130.97,13.78 130.98,13.76 132.56,13.76 132.57,13.75 132.57,11.78 131.63,10.84 131.63,9.7 131.79,9.53 132.17,9.53 132.17,9.55 133.55,10.92 133.55,24.11 134.47,25.04 134.47,27.97 133.12,29.33 133.12,30.59 132.79,30.91 131.01,30.91 130.94,30.98 130.94,31.67 131.55,32.28 132.31,32.28 132.68,32.65 134.66,32.65
+V3.3_WIFI on BOTTOM (solid shape): 139.48,34.96 139.48,32.06 139.17,31.76 134.85,31.76 134.84,31.75 134.45,31.75 134.27,31.92 134.27,32.98 134.54,33.24 137.74,33.24 137.98,33.49 137.98,34.87 138.24,35.14 139.3,35.14
+V3.3S on TOP (solid shape): 33.56,58.38 33.56,55.57 33.19,55.2 28.43,55.2 28.1,55.53 28.1,58.45 28.35,58.7 33.24,58.7
+V3.3S on BOTTOM (solid shape): 130.78,79.97 130.78,78.3 130.54,78.06 127.01,78.06 126.71,78.35 126.71,79.6 127.2,80.08 130.66,80.08
+V3.3S on BOTTOM (solid shape): 20.48,33.74 20.48,33.03 20.15,32.7 9.04,32.7 5,28.65 5,24.62 4.69,24.31 3.55,24.31 3.1,24.76 3.1,29.15 8.09,34.13 20.08,34.13
+V3.3S on BOTTOM (solid shape): outline of 375 points within 29.49,55.41 115.31,82.66
+V3.3S on LAY3 (solid shape): outline of 508 points within 112.77,70.62 131.96,80.17
+V3.3S_AUDIO on BOTTOM (solid shape): 7.39,28.94 7.39,28.67 7.4,28.67 7.4,27.58 7.26,27.44 5.94,27.44 5.59,27.78 5.59,28.58 6.17,29.15 7.18,29.15
+V3.3S_MSATA on TOP (solid shape): 80.21,36 80.21,35.75 78.56,35.75 78.56,35.58 80.21,35.58 80.21,35.25 78.56,35.25 78.56,35.08 80.21,35.08 80.21,33.88 80.1,33.78 76.92,33.78 76.73,33.97 76.73,35.87 76.9,36.05 79.4,36.05 79.41,36.06 80.15,36.06
+V3.3S_MSATA on TOP (solid shape): 80.19,53.05 80.19,52.75 78.56,52.75 78.56,52.58 80.19,52.58 80.19,52.35 80.11,52.27 78.42,52.27 78.25,52.11 78.25,50.7 78.4,50.56 80.17,50.56 80.23,50.5 80.23,50.25 78.56,50.25 78.56,50.08 80.23,50.08 80.23,49.75 78.56,49.75 78.56,49.58 80.23,49.58 80.23,49.25 78.56,49.25 78.56,49.08 80.23,49.08 80.23,48.81 80.18,48.76 76.41,48.76 76.06,49.11 76.06,52.73 76.43,53.1 80.14,53.1
+V3.3S_MSATA on BOTTOM (solid shape): 78.63,36.09 78.63,34.98 78.48,34.83 77.11,34.83 76.95,34.98 76.95,36.17 77.07,36.28 78.44,36.28
+V3.3S_MSATA on BOTTOM (solid shape): 79.44,54.43 79.44,52.42 79.1,52.08 71.43,52.08 71.18,52.33 71.18,52.83 75.08,52.83 75.08,52.77 75.1,52.72 75.12,52.67 75.15,52.62 75.18,52.58 75.22,52.54 75.27,52.51 75.32,52.49 75.37,52.47 75.43,52.46 75.48,52.46 75.54,52.47 75.59,52.49 75.64,52.51 75.69,52.54 75.73,52.58 75.76,52.62 75.79,52.67 75.81,52.72 75.83,52.77 75.83,52.83 75.83,52.88 75.82,52.94 75.8,52.99 75.78,53.04 75.75,53.08 75.71,53.12 75.66,53.16 75.62,53.18 75.57,53.2 75.51,53.22 75.46,53.22 75.4,53.22 75.35,53.2 75.3,53.18 75.25,53.16 75.2,53.12 75.16,53.08 75.13,53.04 75.11,52.99 75.09,52.94 75.08,52.88 75.08,52.83 71.18,52.83 71.18,54.21 71.69,54.73 75.92,54.73 75.93,54.73 79.14,54.73
+V3.3S_MSATA on LAY3 (solid shape): 78.64,52.93 78.64,35.26 78.34,34.96 77.56,34.96 77.22,35.3 77.22,51.8 76.66,52.36 76.66,53.13 76.79,53.26 78.31,53.26
+V3P3_BIOS_SPI on TOP (solid shape): 175.71,49.14 175.71,47.34 175.32,46.95 173.13,46.95 172.89,46.71 172.89,46.17 172.76,46.05 172.12,46.05 171.72,46.44 171.72,47.85 171.77,47.9 173.92,47.9 173.93,47.84 173.94,47.79 173.96,47.74 173.99,47.69 174.03,47.65 174.07,47.61 174.11,47.58 174.16,47.56 174.22,47.54 174.27,47.54 174.33,47.54 174.38,47.54 174.44,47.56 174.49,47.58 174.53,47.61 174.57,47.65 174.61,47.69 174.64,47.74 174.66,47.79 174.67,47.84 174.68,47.9 174.68,47.95 174.67,48.01 174.65,48.06 174.62,48.11 174.59,48.16 174.55,48.19 174.51,48.23 174.46,48.26 174.41,48.28 174.36,48.29 174.3,48.29 174.24,48.29 174.19,48.28 174.14,48.26 174.09,48.23 174.05,48.19 174.01,48.16 173.98,48.11 173.95,48.06 173.93,48.01 173.92,47.95 173.92,47.9 171.77,47.9 171.82,47.95 173.3,47.95 174.59,49.25 175.61,49.25
+V3P3A on TOP (solid shape): 27.6,61.86 27.6,60.18 27.59,60.17 27.55,60 27.59,59.84 27.6,59.83 27.6,56.82 27.5,56.73 24.85,56.73 24.29,57.28 23.46,57.28 22.48,58.25 22.48,58.26 22.09,58.66 19.88,58.66 19.55,58.99 19.55,62.01 19.75,62.21 27.25,62.21
+V3P3A on BOTTOM (solid shape): 139.53,40.34 139.53,36.08 139.25,35.8 137.99,35.8 137.9,35.89 137.9,40.24 138.31,40.65 139.22,40.65
+V3P3A on BOTTOM (solid shape): 170.15,25.87 170.64,25.87 170.86,25.65 170.86,23.8 170.49,23.43 169.43,23.43 169.16,23.54 168.9,23.42 168.64,23.53 168.38,23.43 168.17,23.43 168.08,23.5 168.11,23.61 167.86,24.28 167.62,23.61 167.65,23.5 167.55,23.43 161.71,23.43 161.24,23.9 161.24,25.5 162.11,26.36 169.65,26.36
+V3P3A on BOTTOM (solid shape): outline of 184 points within 167.56,51.6 173.91,60.18
+V3P3A on BOTTOM (solid shape): outline of 793 points within 18.37,35.31 114.51,61.91
+V3P3A on LAY3 (solid shape): outline of 387 points within 108.64,23.33 163.61,57.92
